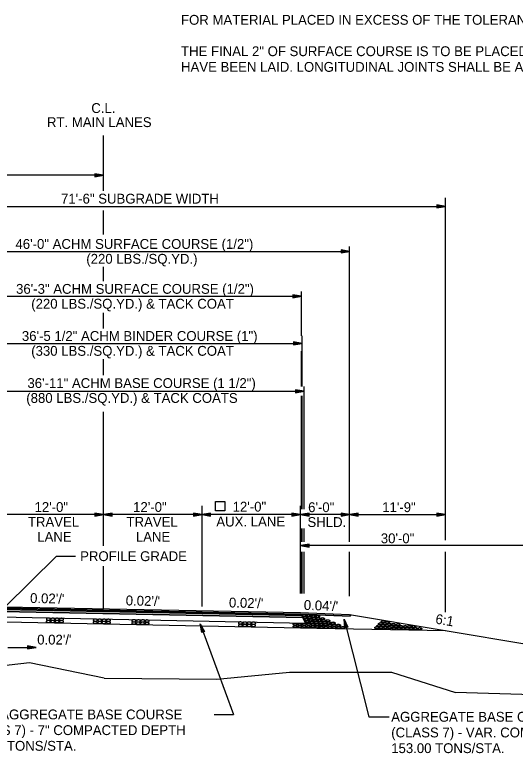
# Model space of a CAD drawing. Extents: x 1734743 to 1735935, y 759845 to 763831.
# Drawn here: x 1735798.9 to 1735859.9, y 763383.7 to 763473.7 of the extents above; entities that cross this region are included whole.
import ezdxf

# ---------------------------------------------------------------- set-up
doc = ezdxf.new("R2010")
doc.units = 0
for name, color, linetype in [('1', 7, 'Continuous'), ('10', 7, 'Continuous'), ('19', 7, 'Continuous'), ('8', 7, 'Continuous'), ('Level 1', 7, 'Continuous'), ('R_Prop Surface', 7, 'Continuous')]:
    doc.layers.add(name, color=color, linetype=linetype)

# ---------------------------------------------------------------- blocks, each defined once
blk = doc.blocks.new('TM')
at = {"layer": '8'}
for p, q in [((-120.309, 21.181), (-119.787, -20.829)), ((0, 0), (-120.309, 21.181)), ((-31.382, 2.945), (-120.176, 10.512)), ((-119.787, -20.829), (0, 0)), ((-119.911, -10.826), (-31.307, -3.057))]:
    blk.add_line(p, q, dxfattribs=at)
blk = doc.blocks.new('ROCKS')
at = {"layer": '1'}
blk.add_spline([(0.013, 0.06), (0.053, 0.053), (0.107, 0.033), (0.133, 0.013), (0.133, -0.007), (0.12, -0.033), (0.107, -0.04), (0.073, -0.053), (0.033, -0.067), (0.013, -0.067), (-0.02, -0.06), (-0.06, -0.053), (-0.087, -0.047), (-0.113, -0.02), (-0.113, -0.007), (-0.107, 0.02), (-0.087, 0.033), (-0.067, 0.047), (-0.033, 0.053), (-0.02, 0.06), (0.013, 0.06)], degree=3, dxfattribs=at)

msp = doc.modelspace()

# ---------------------------------------------------------------- linework, layer by layer
at = {"layer": '10'}
msp.add_lwpolyline([(1735824.491, 763414.338), (1735824.491, 763413.213), (1735823.366, 763413.213), (1735823.366, 763414.338)], close=True, dxfattribs=at)
at = {"layer": '19'}
for p, q in [((1735809.701, 763452.214), (1735809.701, 763458.944)), ((1735809.701, 763454.103), (1735757.701, 763454.103)), ((1735808.651, 763454.287), (1735808.651, 763453.919)), ((1735809.701, 763454.103), (1735808.651, 763454.287)), ((1735809.421, 763454.129), (1735808.651, 763454.191)), ((1735808.651, 763453.919), (1735809.701, 763454.103)), ((1735808.651, 763454.007), (1735809.421, 763454.077)), ((1735851.385, 763409.617), (1735851.385, 763451.355)), ((1735780.014, 763450.309), (1735851.385, 763450.309)), ((1735850.335, 763450.493), (1735850.335, 763450.125)), ((1735851.385, 763450.309), (1735850.335, 763450.493)), ((1735851.105, 763450.335), (1735850.335, 763450.397)), ((1735850.335, 763450.125), (1735851.385, 763450.309)), ((1735809.701, 763446.872), (1735809.701, 763449.798)), ((1735850.335, 763450.213), (1735851.105, 763450.283)), ((1735838.651, 763445.008), (1735838.651, 763444.64)), ((1735839.701, 763444.824), (1735838.651, 763445.008)), ((1735839.421, 763444.85), (1735838.651, 763444.911)), ((1735839.701, 763413.386), (1735839.701, 763445.431)), ((1735793.704, 763444.824), (1735839.701, 763444.824)), ((1735838.651, 763444.64), (1735839.701, 763444.824)), ((1735838.651, 763444.728), (1735839.421, 763444.798)), ((1735809.701, 763441.208), (1735809.701, 763442.956)), ((1735832.77, 763439.531), (1735832.77, 763439.164)), ((1735833.82, 763439.347), (1735832.77, 763439.531)), ((1735833.82, 763434.513), (1735833.82, 763439.954)), ((1735797.582, 763439.347), (1735833.82, 763439.347)), ((1735833.54, 763439.374), (1735832.77, 763439.435)), ((1735832.77, 763439.164), (1735833.82, 763439.347)), ((1735832.77, 763439.251), (1735833.54, 763439.321)), ((1735809.701, 763435.432), (1735809.701, 763437.351)), ((1735833.924, 763428.374), (1735833.924, 763434.513)), ((1735797.478, 763433.607), (1735833.82, 763433.607)), ((1735832.874, 763433.791), (1735832.874, 763433.423)), ((1735833.924, 763433.607), (1735832.874, 763433.791)), ((1735833.644, 763433.633), (1735832.874, 763433.694)), ((1735832.874, 763433.423), (1735833.924, 763433.607)), ((1735832.874, 763433.511), (1735833.644, 763433.58)), ((1735833.82, 763428.374), (1735833.82, 763432.682)), ((1735809.701, 763429.748), (1735809.701, 763431.685)), ((1735833.103, 763427.951), (1735833.103, 763427.584)), ((1735834.153, 763427.768), (1735833.103, 763427.951)), ((1735833.873, 763427.794), (1735833.103, 763427.855)), ((1735834.153, 763413.386), (1735834.153, 763428.374)), ((1735797.249, 763427.768), (1735834.153, 763427.768)), ((1735833.103, 763427.584), (1735834.153, 763427.768)), ((1735833.103, 763427.671), (1735833.873, 763427.741)), ((1735833.82, 763413.386), (1735833.82, 763427.215)), ((1735833.924, 763413.386), (1735833.924, 763427.215)), ((1735809.701, 763408.927), (1735809.701, 763425.284)), ((1735821.701, 763401.56), (1735821.701, 763413.803)), ((1735833.701, 763403.114), (1735833.701, 763413.803)), ((1735839.701, 763409.445), (1735839.701, 763413.803)), ((1735809.701, 763412.753), (1735797.701, 763412.753)), ((1735808.651, 763412.937), (1735808.651, 763412.569)), ((1735809.701, 763412.753), (1735808.651, 763412.937)), ((1735809.421, 763412.779), (1735808.651, 763412.84)), ((1735808.651, 763412.569), (1735809.701, 763412.753)), ((1735808.651, 763412.657), (1735809.421, 763412.727)), ((1735810.751, 763412.937), (1735809.701, 763412.753)), ((1735833.701, 763412.753), (1735809.701, 763412.753)), ((1735809.701, 763412.753), (1735810.751, 763412.569)), ((1735810.751, 763412.84), (1735809.981, 763412.779)), ((1735809.981, 763412.727), (1735810.751, 763412.657)), ((1735810.751, 763412.569), (1735810.751, 763412.937)), ((1735820.651, 763412.937), (1735820.651, 763412.569)), ((1735821.701, 763412.753), (1735820.651, 763412.937)), ((1735821.421, 763412.779), (1735820.651, 763412.84)), ((1735820.651, 763412.569), (1735821.701, 763412.753)), ((1735820.651, 763412.657), (1735821.421, 763412.727)), ((1735822.751, 763412.937), (1735821.701, 763412.753)), ((1735821.701, 763412.753), (1735822.751, 763412.569)), ((1735822.751, 763412.84), (1735821.981, 763412.779)), ((1735821.981, 763412.727), (1735822.751, 763412.657)), ((1735822.751, 763412.569), (1735822.751, 763412.937)), ((1735832.651, 763412.937), (1735832.651, 763412.569)), ((1735833.701, 763412.753), (1735832.651, 763412.937)), ((1735833.421, 763412.779), (1735832.651, 763412.84)), ((1735832.651, 763412.569), (1735833.701, 763412.753)), ((1735832.651, 763412.657), (1735833.421, 763412.727)), ((1735834.751, 763412.937), (1735833.701, 763412.753)), ((1735839.701, 763412.753), (1735833.701, 763412.753)), ((1735833.701, 763412.753), (1735834.751, 763412.569)), ((1735834.751, 763412.84), (1735833.981, 763412.779)), ((1735833.981, 763412.727), (1735834.751, 763412.657)), ((1735834.751, 763412.569), (1735834.751, 763412.937)), ((1735838.651, 763412.937), (1735838.651, 763412.569)), ((1735839.701, 763412.753), (1735838.651, 763412.937)), ((1735839.421, 763412.779), (1735838.651, 763412.84)), ((1735838.651, 763412.569), (1735839.701, 763412.753)), ((1735838.651, 763412.657), (1735839.421, 763412.727)), ((1735840.751, 763412.936), (1735839.701, 763412.752)), ((1735839.701, 763412.752), (1735840.751, 763412.568)), ((1735839.701, 763412.752), (1735851.385, 763412.752)), ((1735840.751, 763412.84), (1735839.981, 763412.778)), ((1735839.981, 763412.726), (1735840.751, 763412.656)), ((1735840.751, 763412.568), (1735840.751, 763412.936)), ((1735850.335, 763412.936), (1735850.335, 763412.568)), ((1735851.385, 763412.752), (1735850.335, 763412.936)), ((1735851.105, 763412.778), (1735850.335, 763412.84)), ((1735850.335, 763412.568), (1735851.385, 763412.752)), ((1735850.335, 763412.656), (1735851.105, 763412.726)), ((1735833.82, 763409.445), (1735833.82, 763411.061)), ((1735833.924, 763409.445), (1735833.924, 763411.061)), ((1735834.153, 763409.445), (1735834.153, 763411.061)), ((1735834.751, 763409.154), (1735833.701, 763408.97)), ((1735863.691, 763408.97), (1735833.701, 763408.97)), ((1735833.701, 763408.97), (1735834.751, 763408.786)), ((1735834.751, 763409.058), (1735833.981, 763408.996)), ((1735833.981, 763408.944), (1735834.751, 763408.874)), ((1735834.751, 763408.786), (1735834.751, 763409.154)), ((1735833.82, 763403.114), (1735833.82, 763408.203)), ((1735833.924, 763403.114), (1735833.924, 763408.203)), ((1735834.153, 763403.114), (1735834.153, 763408.203)), ((1735839.701, 763402.817), (1735839.701, 763408.203)), ((1735851.383, 763400.864), (1735851.383, 763408.203)), ((1735851.385, 763400.928), (1735851.385, 763408.203)), ((1735809.701, 763401.275), (1735809.701, 763406.44)), ((1735797.412, 763400.937), (1735833.996, 763400.205)), ((1735797.412, 763400.937), (1735833.996, 763400.205)), ((1735833.996, 763400.205), (1735797.412, 763400.937)), ((1735797.536, 763401.185), (1735833.869, 763400.458)), ((1735833.869, 763400.458), (1735797.536, 763401.185)), ((1735797.701, 763401.515), (1735833.701, 763400.795)), ((1735797.701, 763401.348), (1735833.701, 763400.628)), ((1735833.701, 763400.795), (1735839.701, 763400.555)), ((1735797.082, 763400.277), (1735834.332, 763399.532)), ((1735797.082, 763400.277), (1735834.332, 763399.532)), ((1735833.701, 763400.628), (1735839.786, 763400.385)), ((1735833.996, 763400.205), (1735833.869, 763400.458)), ((1735834.332, 763399.532), (1735833.996, 763400.205)), ((1735839.03, 763399.997), (1735842.056, 763388.101)), ((1735839.112, 763398.937), (1735839.03, 763399.997)), ((1735839.03, 763399.997), (1735839.466, 763399.024)), ((1735839.701, 763400.555), (1735863.701, 763396.555)), ((1735797.701, 763399.681), (1735835.7, 763398.921)), ((1735821.483, 763399.414), (1735825.524, 763388.387)), ((1735821.672, 763398.368), (1735821.483, 763399.414)), ((1735821.483, 763399.414), (1735822.016, 763398.491)), ((1735821.753, 763398.398), (1735821.552, 763399.143)), ((1735821.598, 763399.16), (1735821.927, 763398.464)), ((1735839.195, 763398.959), (1735839.072, 763399.72)), ((1735839.466, 763399.024), (1735839.112, 763398.937)), ((1735839.119, 763399.733), (1735839.375, 763399.007)), ((1735822.016, 763398.491), (1735821.672, 763398.368)), ((1735835.7, 763398.921), (1735851.385, 763398.608)), ((1735798.043, 763396.543), (1735801.464, 763396.543)), ((1735800.684, 763394.688), (1735789.496, 763393.421)), ((1735809.784, 763392.821), (1735800.684, 763394.688)), ((1735809.784, 763392.821), (1735823.527, 763392.707)), ((1735823.527, 763392.707), (1735832.379, 763393.542)), ((1735832.379, 763393.542), (1735844.79, 763393.542)), ((1735844.79, 763393.542), (1735852.619, 763391.058)), ((1735872.447, 763390.427), (1735852.619, 763391.058)), ((1735823.166, 763388.387), (1735825.524, 763388.387)), ((1735842.056, 763388.101), (1735844.537, 763388.101))]:
    msp.add_line(p, q, dxfattribs=at)
for points in [[(1735806.283, 763407.626), (1735803.928, 763407.626), (1735797.701, 763401.515)], [(1735833.701, 763400.628), (1735797.701, 763401.348), (1735797.616, 763401.345), (1735793.619, 763401.185), (1735793.619, 763401.185), (1735793.704, 763401.355), (1735793.704, 763401.355), (1735797.701, 763401.515), (1735833.701, 763400.795), (1735839.701, 763400.555), (1735839.701, 763400.555), (1735839.786, 763400.385), (1735833.701, 763400.628), (1735833.701, 763400.628), (1735833.701, 763400.628)], [(1735833.869, 763400.458), (1735797.536, 763401.185), (1735797.536, 763401.185), (1735797.616, 763401.345), (1735797.616, 763401.345), (1735797.701, 763401.348), (1735833.377, 763400.634), (1735833.786, 763400.625), (1735833.786, 763400.625), (1735833.869, 763400.458), (1735833.869, 763400.458), (1735833.869, 763400.458)]]:
    msp.add_lwpolyline(points, dxfattribs=at)
at = {"layer": 'R_Prop Surface'}
for p, q in [((1735833.786, 763400.625), (1735833.869, 763400.458)), ((1735833.869, 763400.458), (1735833.996, 763400.205)), ((1735833.996, 763400.205), (1735834.332, 763399.532)), ((1735839.701, 763400.555), (1735839.786, 763400.384))]:
    msp.add_line(p, q, dxfattribs=at)

# ---------------------------------------------------------------- block references
at = {"layer": '19', "xscale": 0.008761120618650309, "yscale": 0.008761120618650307, "rotation": -0.7994241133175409}
msp.add_blockref('TM', (1735801.465, 763396.539), dxfattribs=at)
at = {"layer": 'Level 1'}
for p, xscale, yscale, rotation in [((1735802.954, 763400.009), 2.011654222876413, 2.011654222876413, 0.9336332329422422), ((1735803.498, 763400.001), 2.011654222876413, 2.011654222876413, 0.9336332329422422), ((1735804.019, 763399.992), 2.011654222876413, 2.011654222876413, 0.9336332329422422), ((1735804.562, 763399.984), 2.011654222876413, 2.011654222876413, 0.9336332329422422), ((1735808.677, 763399.895), 2.011654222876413, 2.011654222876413, 0.9336332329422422), ((1735809.22, 763399.886), 2.011654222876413, 2.011654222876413, 0.9336332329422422), ((1735809.742, 763399.878), 2.011654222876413, 2.011654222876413, 0.9336332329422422), ((1735810.285, 763399.87), 2.011654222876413, 2.011654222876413, 0.9336332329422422), ((1735813.383, 763399.807), 2.011654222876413, 2.011654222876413, 0.9336332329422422), ((1735813.926, 763399.798), 2.011654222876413, 2.011654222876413, 0.9336332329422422), ((1735814.448, 763399.79), 2.011654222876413, 2.011654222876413, 0.9336332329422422), ((1735814.99, 763399.782), 2.011654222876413, 2.011654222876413, 0.9336332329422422), ((1735834.17, 763400.457), 2.0116542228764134, -2.011654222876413, 177.9586193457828), ((1735834.295, 763400.198), 2.0116542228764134, -2.011654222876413, 177.9586193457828), ((1735834.44, 763399.937), 2.0116542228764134, -2.011654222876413, 177.9586193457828), ((1735834.703, 763400.428), 2.0116542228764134, -2.011654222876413, 177.9586193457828), ((1735834.821, 763400.164), 2.0116542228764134, -2.011654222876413, 177.9586193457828), ((1735834.985, 763399.902), 2.0116542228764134, -2.011654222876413, 177.9586193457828), ((1735835.289, 763400.385), 2.011654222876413, -2.0116542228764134, 177.95871721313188), ((1735835.376, 763400.124), 2.011654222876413, -2.0116542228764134, 177.95871721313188), ((1735835.514, 763399.869), 2.0116542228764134, -2.011654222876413, 177.9586193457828), ((1735835.807, 763400.346), 2.011654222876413, -2.0116542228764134, 177.95871721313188), ((1735835.898, 763400.078), 2.011654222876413, -2.0116542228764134, 177.95871721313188), ((1735836.037, 763399.821), 2.011654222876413, -2.0116542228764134, 177.95871721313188), ((1735836.403, 763400.059), 2.011654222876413, -2.0116542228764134, 177.95871721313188), ((1735836.542, 763399.806), 2.011654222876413, -2.0116542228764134, 177.95871721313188), ((1735837.053, 763399.804), 2.011654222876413, -2.0116542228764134, 177.95871721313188), ((1735802.945, 763399.729), 2.011654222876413, 2.011654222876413, 0.9336332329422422), ((1735803.488, 763399.721), 2.011654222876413, 2.011654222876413, 0.9336332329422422), ((1735804.01, 763399.713), 2.011654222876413, 2.011654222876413, 0.9336332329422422), ((1735804.552, 763399.704), 2.011654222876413, 2.011654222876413, 0.9336332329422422), ((1735808.667, 763399.615), 2.011654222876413, 2.011654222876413, 0.9336332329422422), ((1735809.211, 763399.606), 2.011654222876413, 2.011654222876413, 0.9336332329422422), ((1735809.732, 763399.598), 2.011654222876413, 2.011654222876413, 0.9336332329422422), ((1735810.275, 763399.59), 2.011654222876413, 2.011654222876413, 0.9336332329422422), ((1735813.373, 763399.527), 2.011654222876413, 2.011654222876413, 0.9336332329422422), ((1735813.917, 763399.518), 2.011654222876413, 2.011654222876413, 0.9336332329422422), ((1735814.438, 763399.51), 2.011654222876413, 2.011654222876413, 0.9336332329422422), ((1735814.981, 763399.502), 2.011654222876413, 2.011654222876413, 0.9336332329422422), ((1735826.362, 763399.263), 2.011654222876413, 2.011654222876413, 0.9336332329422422), ((1735826.372, 763399.543), 2.011654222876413, 2.011654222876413, 0.9336332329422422), ((1735826.906, 763399.254), 2.011654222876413, 2.011654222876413, 0.9336332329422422), ((1735826.915, 763399.534), 2.011654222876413, 2.011654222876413, 0.9336332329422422), ((1735827.427, 763399.246), 2.011654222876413, 2.011654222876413, 0.9336332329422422), ((1735827.437, 763399.526), 2.011654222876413, 2.011654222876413, 0.9336332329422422), ((1735827.97, 763399.238), 2.011654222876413, 2.011654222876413, 0.9336332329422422), ((1735827.979, 763399.518), 2.011654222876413, 2.011654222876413, 0.9336332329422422), ((1735833.086, 763399.389), 2.0116542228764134, -2.011654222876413, 177.9586193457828), ((1735833.09, 763399.109), 2.0116542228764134, -2.011654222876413, 177.9586193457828), ((1735833.656, 763399.387), 2.0116542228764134, -2.011654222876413, 177.9586193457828), ((1735833.661, 763399.107), 2.0116542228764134, -2.011654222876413, 177.9586193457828), ((1735834.179, 763399.105), 2.0116542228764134, -2.011654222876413, 177.9586193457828), ((1735834.18, 763399.398), 2.0116542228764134, -2.011654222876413, 177.9586193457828), ((1735834.587, 763399.689), 2.0116542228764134, -2.011654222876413, 177.9586193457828), ((1735834.715, 763399.103), 2.0116542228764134, -2.011654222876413, 177.9586193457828), ((1735834.716, 763399.396), 2.0116542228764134, -2.011654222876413, 177.9586193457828), ((1735835.128, 763399.634), 2.0116542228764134, -2.011654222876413, 177.9586193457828), ((1735835.249, 763399.101), 2.0116542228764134, -2.011654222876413, 177.9586193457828), ((1735835.25, 763399.372), 2.0116542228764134, -2.011654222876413, 177.9586193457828), ((1735835.65, 763399.601), 2.0116542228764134, -2.011654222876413, 177.9586193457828), ((1735835.781, 763399.055), 2.0116542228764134, -2.011654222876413, 177.9586193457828), ((1735835.782, 763399.326), 2.0116542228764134, -2.011654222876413, 177.9586193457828), ((1735836.166, 763399.563), 2.011654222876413, -2.0116542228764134, 177.95871721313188), ((1735836.284, 763399.306), 2.011654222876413, -2.0116542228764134, 177.95871721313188), ((1735836.284, 763399.026), 2.011654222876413, -2.0116542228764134, 177.95871721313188), ((1735836.677, 763399.558), 2.011654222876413, -2.0116542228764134, 177.95871721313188), ((1735836.795, 763399.306), 2.011654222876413, -2.0116542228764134, 177.95871721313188), ((1735836.808, 763399.03), 2.011654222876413, -2.0116542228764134, 177.95871721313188), ((1735837.189, 763399.542), 2.011654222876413, -2.0116542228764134, 177.95871721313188), ((1735837.321, 763399.281), 2.011654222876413, -2.0116542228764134, 177.95871721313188), ((1735837.321, 763399.006), 2.011654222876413, -2.0116542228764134, 177.95871721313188), ((1735837.698, 763399.53), 2.011654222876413, -2.0116542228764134, 177.95871721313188), ((1735837.835, 763399.275), 2.011654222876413, -2.0116542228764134, 177.95871721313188), ((1735837.835, 763398.995), 2.011654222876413, -2.0116542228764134, 177.95871721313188), ((1735838.36, 763399.261), 2.011654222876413, -2.0116542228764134, 177.95871721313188), ((1735838.36, 763398.99), 2.011654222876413, -2.0116542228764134, 177.95871721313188), ((1735838.873, 763398.982), 2.011654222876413, -2.0116542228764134, 177.95871721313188), ((1735843.022, 763398.951), 2.011654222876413, -2.011654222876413, 178.17361855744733), ((1735843.289, 763399.188), 2.011654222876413, -2.011654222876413, 178.17361855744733), ((1735843.506, 763399.441), 2.011654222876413, -2.011654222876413, 178.17361855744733), ((1735843.55, 763398.945), 2.011654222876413, -2.011654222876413, 178.17361855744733), ((1735843.787, 763399.199), 2.011654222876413, -2.011654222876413, 178.17361855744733), ((1735843.816, 763399.686), 2.011654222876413, -2.011654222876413, 178.17361855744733), ((1735844.016, 763399.429), 2.011654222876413, -2.011654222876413, 178.17361855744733), ((1735844.065, 763398.975), 2.011654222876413, -2.011654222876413, 178.17361855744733), ((1735844.316, 763399.18), 2.011654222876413, -2.011654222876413, 178.17361855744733), ((1735844.325, 763399.63), 2.011654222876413, -2.011654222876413, 178.17361855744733), ((1735844.534, 763399.394), 2.011654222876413, -2.011654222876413, 178.17361855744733), ((1735844.587, 763398.942), 2.011654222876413, -2.011654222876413, 178.17361855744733), ((1735844.839, 763399.147), 2.011654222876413, -2.011654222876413, 178.17361855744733), ((1735845.057, 763399.361), 2.011654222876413, -2.011654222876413, 178.17361855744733), ((1735845.145, 763398.898), 2.011654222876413, -2.011654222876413, 178.17361855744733), ((1735845.397, 763399.103), 2.011654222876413, -2.011654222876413, 178.17361855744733), ((1735845.614, 763399.317), 2.011654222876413, -2.011654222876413, 178.17361855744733), ((1735845.753, 763398.898), 2.011654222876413, -2.011654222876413, 178.17361855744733), ((1735846.005, 763399.103), 2.011654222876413, -2.011654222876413, 178.17361855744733), ((1735846.244, 763398.882), 2.011654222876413, -2.011654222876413, 178.17361855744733), ((1735846.498, 763399.097), 2.011654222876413, -2.011654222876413, 178.17361855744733), ((1735846.74, 763398.874), 2.011654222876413, -2.011654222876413, 178.17361855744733), ((1735847.004, 763399.104), 2.011654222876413, -2.011654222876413, 178.17361855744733), ((1735847.236, 763398.864), 2.011654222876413, -2.011654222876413, 178.17361855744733), ((1735847.525, 763399.088), 2.011654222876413, -2.011654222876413, 178.17361855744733), ((1735847.736, 763398.85), 2.011654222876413, -2.011654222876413, 178.17361855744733), ((1735848.257, 763398.844), 2.011654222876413, -2.011654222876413, 178.17361855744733)]:
    msp.add_blockref('ROCKS', p, dxfattribs=dict(at, xscale=xscale, yscale=yscale, rotation=rotation))

# ---------------------------------------------------------------- texts
at = {"layer": '1'}
for s, p in [('FOR MATERIAL PLACED IN EXCESS OF THE TOLERANCE INDICATED.', (1735819.145, 763472.444)), ('THE FINAL 2" OF SURFACE COURSE IS TO BE PLACED AFTER ALL OTHER COURSES', (1735819.145, 763468.62)), ('HAVE BEEN LAID. LONGITUDINAL JOINTS SHALL BE AT THE LANE LINES.', (1735819.145, 763466.709))]:
    msp.add_text(s, height=1.2, dxfattribs=at).set_placement(p)
at = {"layer": '19'}
for s, p in [('C.L.', (1735808.208, 763461.69)), ('RT. MAIN LANES', (1735802.803, 763459.974)), ('71\'-6" SUBGRADE WIDTH', (1735804.515, 763450.647)), ('46\'-0" ACHM SURFACE COURSE (1/2")', (1735798.96, 763445.13)), ('(220 LBS./SQ.YD.)', (1735807.596, 763443.318)), ('36\'-3" ACHM SURFACE COURSE (1/2")', (1735799.033, 763439.654)), ('(220 LBS./SQ.YD.) & TACK COAT', (1735800.88, 763437.841)), ('36\'-5 1/2" ACHM BINDER COURSE (1")', (1735799.742, 763433.913)), ('(330 LBS./SQ.YD.) & TACK COAT', (1735800.88, 763432.1)), ('36\'-11" ACHM BASE COURSE (1 1/2")', (1735800.419, 763428.172)), ('(880 LBS./SQ.YD.) & TACK COATS', (1735800.277, 763426.36)), ('12\'-0" ', (1735825.437, 763413.107)), ('12\'-0"', (1735801.283, 763413.068)), ('12\'-0"', (1735813.306, 763413.068)), ('6\'-0"', (1735834.639, 763413.045)), ('11\'-9"', (1735843.669, 763413.049)), ('AUX. LANE', (1735823.448, 763411.294)), ('TRAVEL', (1735800.475, 763411.255)), ('TRAVEL', (1735812.498, 763411.255)), ('SHLD.', (1735834.558, 763411.232)), ('LANE', (1735801.618, 763409.443)), ('LANE', (1735813.641, 763409.443)), ('30\'-0"', (1735843.497, 763409.254)), ('PROFILE GRADE', (1735806.845, 763407.076)), ("0.02'/'", (1735801.61, 763396.905))]:
    msp.add_text(s, height=1.2, dxfattribs=at).set_placement(p)
for s, rotation, p in [("0.02'/'", 358.63856, (1735800.729, 763401.981)), ("0.02'/'", 358.63856, (1735812.391, 763401.687)), ("0.02'/'", 358.63856, (1735824.973, 763401.435)), ("0.04'/'", 357.83981, (1735834.095, 763401.14)), ('6:1', 350.54888, (1735850.095, 763399.476)), ('36\'-0" AGGREGATE BASE COURSE', 360, (1735792.569, 763387.787)), ('AGGREGATE BASE COURSE', 360, (1735844.769, 763387.501)), ('(CLASS 7) - 7" COMPACTED DEPTH', 360, (1735792.569, 763385.875)), ('(CLASS 7) - VAR. COMPACTED DEPTH', 360, (1735844.769, 763385.589)), ('163.25 TONS/STA.', 360, (1735792.569, 763383.963)), ('153.00 TONS/STA.', 360, (1735844.769, 763383.677))]:
    msp.add_text(s, height=1.2, rotation=rotation, dxfattribs=at).set_placement(p)

doc.saveas('drawing.dxf')
